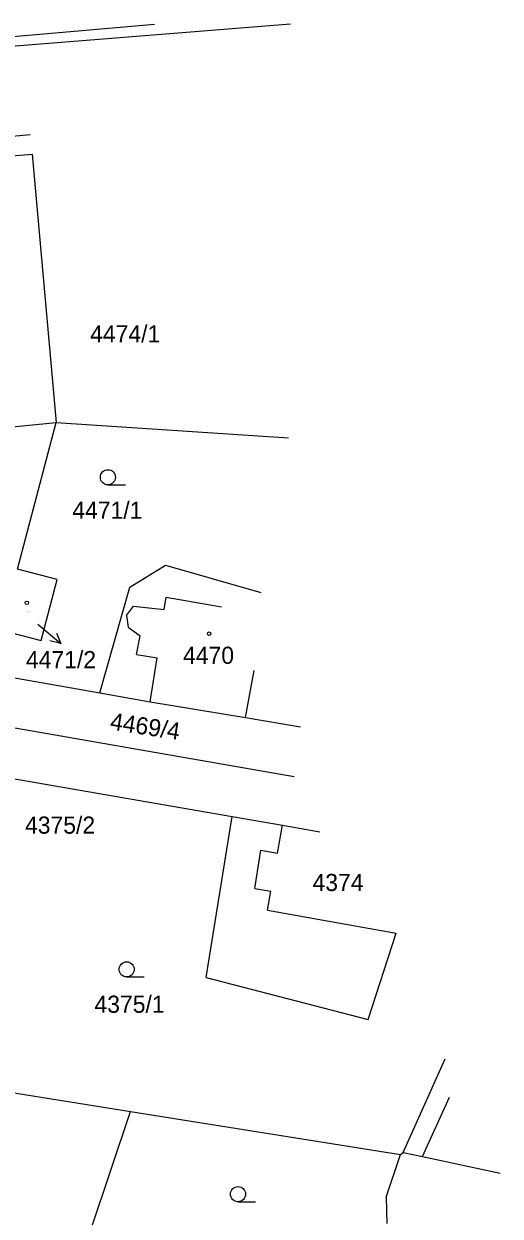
# Model space of a CAD drawing. Extents: x -735092 to -733385, y -1122435 to -1118992.
# Drawn here: x -734292.6 to -734245.4, y -1119855 to -1119736.9 of the extents above; entities that cross this region are included whole.
import ezdxf

# ---------------------------------------------------------------- set-up
doc = ezdxf.new("R2010")
doc.units = 0
for name, color, linetype in [('Vrstva 1', 7, 'Continuous'), ('Vrstva 16', 7, 'Continuous'), ('Vrstva 18', 7, 'Continuous'), ('Vrstva 19', 7, 'Continuous'), ('Vrstva 25', 7, 'Continuous'), ('Vrstva 4', 7, 'Continuous')]:
    doc.layers.add(name, color=color, linetype=linetype)

msp = doc.modelspace()

# ---------------------------------------------------------------- linework, layer by layer
at = {"layer": 'Vrstva 1'}
for points in [[(-734368.21, -1119745), (-734266.19, -1119736.86)], [(-734320.66, -1119740.46), (-734279.66, -1119736.88)], [(-734317, -1119750.12), (-734292.01, -1119747.82)], [(-734312.77, -1119751.49), (-734291.79, -1119749.76)], [(-734291.79, -1119749.76), (-734289.43, -1119776.34)], [(-734312.18, -1119778.6), (-734289.43, -1119776.34)], [(-734293.27, -1119790.88), (-734289.43, -1119776.34)], [(-734289.43, -1119776.34), (-734266.38, -1119777.85)], [(-734282.11, -1119792.64), (-734278.58, -1119790.46)], [(-734278.58, -1119790.46), (-734269.13, -1119793.17)], [(-734289.33, -1119791.9), (-734293.27, -1119790.88)], [(-734290.9, -1119797.93), (-734289.33, -1119791.9)], [(-734285.1, -1119803.12), (-734282.11, -1119792.64)], [(-734294.86, -1119796.92), (-734290.9, -1119797.93)], [(-734295.99, -1119801.2), (-734285.1, -1119803.12)], [(-734285.1, -1119803.12), (-734280.09, -1119804.01)], [(-734280.09, -1119804.01), (-734270.65, -1119805.57)], [(-734296.95, -1119805.99), (-734265.82, -1119811.41)], [(-734270.65, -1119805.57), (-734265.2, -1119806.5)], [(-734294.67, -1119811.45), (-734271.96, -1119815.37)], [(-734274.54, -1119831.31), (-734271.96, -1119815.37)], [(-734271.96, -1119815.37), (-734266.98, -1119816.23)], [(-734266.98, -1119816.23), (-734263.28, -1119816.9)], [(-734258.49, -1119835.48), (-734255.72, -1119826.91)], [(-734274.54, -1119831.31), (-734258.49, -1119835.48)], [(-734255.01, -1119848.64), (-734250.83, -1119839.36)], [(-734303.92, -1119841.09), (-734282.04, -1119844.57)], [(-734289.84, -1119867.82), (-734282.04, -1119844.57)], [(-734282.04, -1119844.57), (-734255.26, -1119848.83)], [(-734256.69, -1119853.08), (-734255.26, -1119848.83)], [(-734255.26, -1119848.83), (-734255.01, -1119848.64)], [(-734255.01, -1119848.64), (-734253.09, -1119849.05)], [(-734253.09, -1119849.05), (-734245.39, -1119850.71)], [(-734256.69, -1119853.08), (-734256.63, -1119855.69)]]:
    msp.add_lwpolyline(points, dxfattribs=at)
at = {"layer": 'Vrstva 25'}
for points in [[(-734284.29, -1119782.52), (-734282.54, -1119782.52)], [(-734291.25, -1119796.31), (-734288.952, -1119798.238)], [(-734289.397, -1119797.212), (-734288.952, -1119798.238), (-734290.04, -1119797.978)], [(-734282.43, -1119831.26), (-734280.68, -1119831.26)], [(-734271.39, -1119853.52), (-734269.64, -1119853.52)]]:
    msp.add_lwpolyline(points, dxfattribs=at)
for centre, radius in [((-734284.29, -1119781.77), 0.75), ((-734292.33, -1119794.2), 0.175), ((-734274.25, -1119797.26), 0.175), ((-734282.43, -1119830.51), 0.75), ((-734271.39, -1119852.77), 0.75)]:
    msp.add_circle(centre, radius, dxfattribs=at)
at = {"layer": 'Vrstva 4'}
for points in [[(-734278.72, -1119794.86), (-734278.51, -1119793.65)], [(-734278.51, -1119793.65), (-734273.01, -1119794.61)], [(-734282.44, -1119795.46), (-734281.74, -1119794.53)], [(-734281.74, -1119794.53), (-734278.72, -1119794.86)], [(-734282.44, -1119795.46), (-734282.27, -1119796.62)], [(-734282.27, -1119796.62), (-734281.08, -1119797.47)], [(-734281.45, -1119799.33), (-734281.08, -1119797.47)], [(-734281.45, -1119799.33), (-734279.4, -1119799.64)], [(-734280.09, -1119804.01), (-734279.4, -1119799.64)], [(-734270.65, -1119805.57), (-734269.8, -1119800.9)], [(-734267.47, -1119818.99), (-734266.98, -1119816.23)], [(-734269.73, -1119822.51), (-734269.12, -1119818.69)], [(-734269.12, -1119818.69), (-734267.47, -1119818.99)], [(-734269.73, -1119822.51), (-734268.13, -1119822.76)], [(-734268.47, -1119824.66), (-734268.13, -1119822.76)], [(-734268.47, -1119824.66), (-734255.72, -1119826.91)], [(-734253.09, -1119849.05), (-734250.41, -1119843.17)]]:
    msp.add_lwpolyline(points, dxfattribs=at)

# ---------------------------------------------------------------- texts
at = {"layer": 'Vrstva 16'}
for s, p in [('4471/2', (-734292.418, -1119800.68)), ('4375/2', (-734292.51, -1119817.07))]:
    msp.add_text(s, height=1.7, dxfattribs=at).set_placement(p)
at = {"layer": 'Vrstva 18'}
for s, p in [('4474/1', (-734286.05, -1119768.41)), ('4471/1', (-734287.818, -1119785.88)), ('4375/1', (-734285.62, -1119834.81))]:
    msp.add_text(s, height=1.7, dxfattribs=at).set_placement(p)
msp.add_text('4469/4', height=1.7, rotation=351.30279, dxfattribs=at).set_placement((-734284.153, -1119806.743))
at = {"layer": 'Vrstva 19'}
for s, height, p in [('4471/2', 0.1, (-734292.404, -1119795.15)), ('4470', 1.7, (-734276.84, -1119800.25)), ('4374', 1.7, (-734264, -1119822.75))]:
    msp.add_text(s, height=height, dxfattribs=at).set_placement(p)

doc.saveas('drawing.dxf')
